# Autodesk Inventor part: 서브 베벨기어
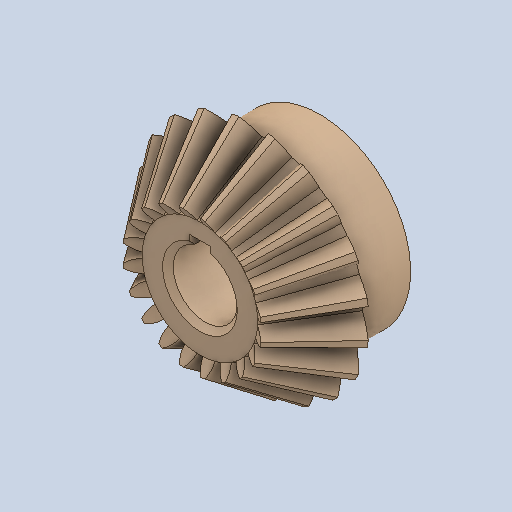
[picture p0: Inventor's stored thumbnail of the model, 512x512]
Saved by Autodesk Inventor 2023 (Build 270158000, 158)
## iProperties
Created: 2025-04
Part Number: 서브 베벨기어
Material: 강철, 탄소
Document SubType Name: Modeling
Designer: user
Density: 7.87 g/cm^3
Appearance: 기본값
Author: jhkim
Revision Number: 1
Sending System: Autodesk Inventor 2026
Preprocessor: ST-DEVELOPER v20.1
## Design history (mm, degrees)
node "복구된 형상1"
  node "스케치11"
feature "Solid1"
node "스케치10"
node "솔리드1"
